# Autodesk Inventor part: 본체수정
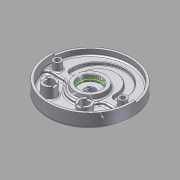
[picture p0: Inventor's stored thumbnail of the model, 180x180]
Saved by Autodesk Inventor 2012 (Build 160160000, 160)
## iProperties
Company: 한국ATC센터
Created: 2015-04
Part Number: 본체수정
Document SubType Name: Modeling
Designer: KYOUNG IL JANG
Density: 2.71 g/cm^3
Material: 알루미늄-6061
Mass: 1082.17 g
Surface Area: 1035.76 cm^2
Volume: 399.325 cm^3
Author: KYOUNG IL JANG
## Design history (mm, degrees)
sketch "스케치1"
  geometry: L1 (-59, -19)-(-59, 19); L2 (59, 19)-(59, -19); L3 (-41, 19)-(-41, -19); L4 (41, -19)-(41, 19); L5 (59, 5)-(41, 5); L6 (-41, 5)-(-59, 5); C1 r 90 at (0, 0); C2 r 95 at (0, 0); A1 r 59 centre (0, 19) between (59, 19) and (-59, 19); A2 r 59 centre (0, -19) between (-59, -19) and (59, -19); A3 r 41 centre (0, -19) between (-41, -19) and (41, -19); A4 r 41 centre (0, 19) between (41, 19) and (-41, 19); 2 further points
  constraints: 12 end point, 8 point on circle, 6 centre point, 5 point on line, 4 tangent, 2 parallel, 1 coincident, 1 collinear, 1 horizontal alignment, 1 midpoint, 1 perpendicular, 1 vertical, 1 vertical alignment, 3 other
  dimensions: "d2" = 180 diameter of C1; "d3" = 156 dimension on A2 A1; "d4" = 118 distance between parallel lines of L2 L1; "d5" = 18 distance between parallel lines of L2 L4; "d8" = 190 diameter of C2; "d117" = 5 distance from line of L5 point (0, 0)
extrude "돌출1" new body sketch "스케치1" distance "d6" = 14; taper "d7" = 0 deg
extrude "돌출2" join sketch "스케치1" distance "d9" = 13; taper "d10" = 0 deg
extrude "돌출3" cut sketch "스케치1" distance "d11" = 7; taper "d12" = 0 deg
sketch "스케치2"
  geometry: C1 r 11.5 at (0, 0); 1 further point
  constraints: 1 centre point, 1 coincident
  dimensions: "d13" = 23 diameter of C1
extrude "돌출4" cut sketch "스케치2" stored distance "d14" = 7; taper "d15" = 0 deg
fillet "모깎기1"
fillet "모깎기2"
sketch "스케치3"
  geometry: L1 (-89.658, 7.844)-(-94.638, 8.28); L2 (89.658, 7.844)-(94.638, 8.28); L3 (0, 0)-(0, -90); A1 r 95 centre (0, 0) between (-94.638, 8.28) and (94.638, 8.28) reference; A2 r 90 centre (0, 0) between (-89.658, 7.844) and (89.658, 7.844) reference; 1 further point
  constraints: 6 end point, 5 point on circle, 1 point on line, 1 vertical, 1 other
  dimensions: "d16" = 190 deg dimension on L2 L1
extrude "돌출5" join sketch "스케치3" distance "d17" = 5; taper "d18" = 0 deg
hole "구멍1" diameter "d21" = 50; stored, may be unused: countersink angle "d25" = 90 deg, drill point angle "d27" = 0 deg; dims "d19" = 10, "d20" = 10, "d22" = 6, "d23" = 4, "d24" = 2, "d26" = 5
fillet "모깎기3" dims "d28" = 0.3
fillet "모깎기5" dims "d30" = 3
sketch "스케치4"
  geometry: C1 r 35 at (0, 0); C2 r 25 at (0, 0); 1 further point
  constraints: 2 centre point, 1 coincident
  dimensions: "d32" = 70 diameter of C1 (derived); "d36" = 10 radial gap between concentric circles of C1 C2
extrude "돌출6" join sketch "스케치4" distance "d33" = 10; taper "d34" = 0 deg
feature "면 기울기2" dims angle "d37" = 10 deg
chamfer "모따기1" distance "d39" = 1; stored, may be unused: second distance "d40" = 2, angle "d41" = 45 deg
fillet "모깎기7" dims "d42" = 5
sketch "스케치5"
  geometry: L1 (-40.249, -12)-(-89.196, -12); L2 (40.249, -12)-(89.196, -12); A1 r 90 centre (0, 0) between (-89.196, -12) and (89.196, -12) reference; A2 r 42 centre (0, 0) between (-40.249, -12) and (40.249, -12); 1 further point
  constraints: 4 end point, 4 point on circle, 1 centre point, 1 collinear, 1 horizontal, 1 point on line
  dimensions: "d43" = 48 radial gap between concentric circles of A1 A2; "d44" = 12 distance from line of point (0, 0) L1
extrude "돌출7" cut sketch "스케치5" stored distance "d45" = 10; taper "d46" = 0 deg
fillet "모깎기8" dims "d47" = 10
chamfer "모따기2" distance "d49" = 1; stored, may be unused: second distance "d50" = 2, angle "d51" = 45 deg
sketch "스케치7"
  geometry: L1 (36.062, 36.062)-(50.912, 50.912); L2 (-36.062, 36.062)-(-50.912, 50.912); A1 r 72 centre (0, 0) between (50.912, 50.912) and (-50.912, 50.912); A2 r 51 centre (0, 0) between (36.062, 36.062) and (-36.062, 36.062); 1 further point
  constraints: 8 point on circle, 4 end point, 2 centre point, 2 point on line, 1 coincident, 1 horizontal alignment
  dimensions: "d54" = 72 radius of A1; "d55" = 21 radial gap between concentric circles of A1 A2; "d56" = 90 deg angle of L2 L1
extrude "돌출8" join sketch "스케치7" distance "d57" = 5; taper "d58" = 0 deg
fillet "모깎기10" dims "d59" = 5
fillet "모깎기11" dims "d60" = 5
fillet "모깎기12" dims "d61" = 3
sketch "스케치8"
  geometry: C1 r 9 at (74, 0); C2 r 9 at (-74, 0); A1 r 74 centre (0, 0) between (74, 0) and (-74, 0); 1 further point
  constraints: 3 centre point, 2 horizontal alignment, 2 point on circle, 1 coincident, 1 equal radius
  dimensions: "d64" = 18 diameter of C1; "d65" = 148 diameter of A1
extrude "돌출9" join sketch "스케치8" stored distance "d66" = 5; taper "d67" = 0 deg
sketch "스케치11"
  geometry: C1 r 15 at (40, -52); C2 r 15 at (-40, -52); 1 further point
  constraints: 2 centre point, 1 equal radius, 1 horizontal alignment
  dimensions: "d83" = 52 vertical distance of point (0, 0) C1.centre; "d84" = 80 distance of C2.centre C1.centre; "d85" = 40 horizontal distance of point (0, 0) C1.centre (= 0.5 x d84); "d86" = 30 diameter of C1
extrude "돌출10" join sketch "스케치11" stored distance "d87" = 5; taper "d88" = 0 deg
node "구멍3"
node "구멍5"
hole "구멍6" diameter "d93" = 20; stored, may be unused: countersink angle "d97" = 90 deg, drill point angle "d99" = 118 deg; dims "d91" = 10, "d92" = 10, "d94" = 6, "d95" = 4, "d96" = 2, "d98" = 8
hole "구멍7" diameter "d102" = 20; stored, may be unused: countersink angle "d106" = 90 deg, drill point angle "d108" = 118 deg; dims "d100" = 10, "d101" = 10, "d103" = 6, "d104" = 4, "d105" = 2, "d107" = 8
sketch "스케치13"
  geometry: L1 (6, -13.748)-(6, -8); L2 (6, 8)-(6, 13.748); L3 (-6, -13.748)-(-6, -8); L4 (-6, 8)-(-6, 13.748); L5 (-66.252, -6)-(-72, -6); L6 (-88, -6)-(-93.748, -6); L7 (-66.252, 6)-(-72, 6); L8 (-88, 6)-(-93.748, 6); A1 r 15 centre (0, 0) between (6, -13.748) and (6, 13.748) reference; A2 r 10 centre (0, 0) between (6, -8) and (6, 8) reference; A3 r 15 centre (-80, 0) between (-66.252, -6) and (-93.748, -6) reference; A4 r 10 centre (-80, 0) between (-72, -6) and (-88, -6) reference; 1 further point
  constraints: 16 end point, 16 point on circle, 4 equal length, 3 collinear, 2 point on line, 1 perpendicular, 1 vertical
  dimensions: "d109" = 12 distance between parallel lines of L3 L1; "d110" = 6 distance from line of A1.centre L1 (= 0.5 x d109); "d111" = 12 distance between parallel lines of L7 L5; "d112" = 6 distance from line of A3.centre L5 (= 0.5 x d111)
extrude "돌출12" cut sketch "스케치13" distance "d113" = 3; taper "d114" = 0 deg
fillet "모깎기13" dims "d115" = 3
fillet "모깎기14" dims "d116" = 1
sketch "스케치14"
  geometry: C1 r 25 at (0, 0); C2 r 11.5 at (0, 0) reference; 1 further point
  constraints: 1 centre point, 1 coincident
  dimensions: "d120" = 50 diameter of C1
extrude "돌출13" join sketch "스케치14" distance "d121" = 12; taper "d122" = 0 deg
feature "면 기울기3" dims angle "d123" = 15 deg
fillet "모깎기15" dims "d124" = 3
chamfer "모따기3" distance "d125" = 1; stored, may be unused: second distance "d126" = 2, angle "d127" = 45 deg
sketch "스케치6"
  geometry: C1 r 68 at (0, 0); 1 further point
  constraints: 1 centre point, 1 other
  dimensions: "d119" = 136 diameter of C1
node "솔리드1"
sketch "스케치9"
  geometry: 1 further point
hole "구멍2" sketch "스케치9" diameter "d68" = 11; stored, may be unused: countersink angle "d72" = 90 deg, drill point angle "d74" = 0 deg; dims "d69" = 6, "d70" = 18, "d71" = 11, "d73" = 8
sketch "스케치10"
  geometry: 1 further point
hole "구멍4" sketch "스케치10" diameter "d75" = 11; stored, may be unused: countersink angle "d79" = 90 deg, drill point angle "d81" = 0 deg; dims "d76" = 6, "d77" = 18, "d78" = 11, "d80" = 8
